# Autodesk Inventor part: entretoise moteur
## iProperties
Author: Administrateur
Created: 2001-04
Part Number: entretoise moteur
Material: Par défaut
Document SubType Name: Modélisation
Designer: Administrateur
Control State: 0
Master: False
Checked Out: False
PropertySet Name: Design Tracking Control
Shininess: 20.0
PropertySet Name: _Private Model Information
Length Units: 11269
Angle Units: 11283
Time Units: 11279
Mass Units: 11290
Length Display Precision: 3
Angle Display Precision: 2
Compacted: False
Density: 0.0
Volumn: 0.0
Area: 0.0
PropertySet Name: Model Information
